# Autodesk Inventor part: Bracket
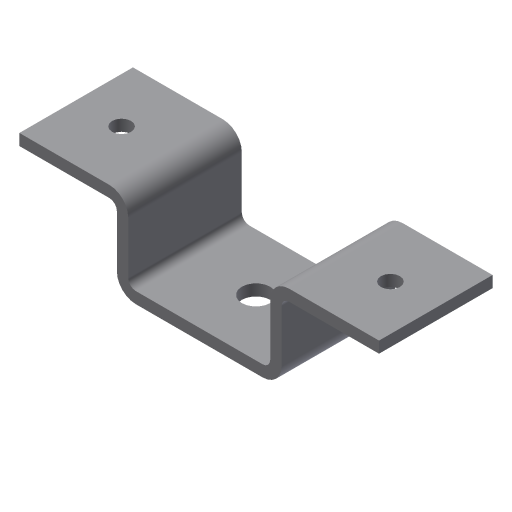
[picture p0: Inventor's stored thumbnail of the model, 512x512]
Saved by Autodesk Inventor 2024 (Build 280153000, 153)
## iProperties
Part Number: Bracket
Document SubType Name: Modeling
Created: 2003-01
Designer: Owner
Density: 1 g/cm^3
Material: Generic
Appearance: Default
Control State: 0
Master: False
Checked Out: False
Shininess: 64.0
Length Units: 11269
Angle Units: 11279
Time Units: 11290
Mass Units: 11283
Length Display Precision: 3
Angle Display Precision: 2
Compacted: True
Density: 0.0
Volumn: 0.0
Area: 0.0
PropertySet Name: Model Information
Author: Owner
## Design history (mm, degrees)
sketch "Sketch2"
  geometry: L1 (487.39, 112.858)-(199.89, 112.858); L2 (199.89, 112.858)-(199.89, -95.142); L3 (199.89, -95.142)-(-175.11, -95.142); L4 (-175.11, -95.142)-(-175.11, 112.858); L5 (-175.11, 112.858)-(-462.61, 112.858); L6 (-462.61, 82.858)-(-205.11, 82.858); L7 (-205.11, 82.858)-(-205.11, -125.142); L8 (-205.11, -125.142)-(229.89, -125.142); L9 (229.89, -125.142)-(229.89, 82.858); L10 (229.89, 82.858)-(487.39, 82.858); L11 (487.39, 112.858)-(487.39, 82.858); L12 (-462.61, 112.858)-(-462.61, 82.858)
  constraints: 24 end point, 5 parallel, 3 perpendicular, 2 collinear, 2 equal length, 1 horizontal, 4 other
  dimensions: "d0" = 375 distance between parallel lines of L4 L2; "d1" = 950 distance of L5.end L1.start; "d2" = 30 distance between parallel lines of L1 L10; "d3" = 238 distance between parallel lines of L5 L8
extrude "Extrusion1" new body sketch "Sketch2" stored distance "d4" = 300; taper "d5" = 0 deg
fillet "Fillet1" dims "d6" = 20
fillet "Fillet2" dims "d7" = 50
sketch "Sketch3"
  geometry: L1 (237.5, 300)-(0, 300) reference; L2 (0, 300)-(0, 0) reference; 1 further point
  dimensions: "d8" = 120 distance from line of L2 point (120, 150); "d9" = 150 distance from line of L1 point (120, 150)
hole "Hole1" sketch "Sketch3" at (120, 150) diameter "d10" = 50; stored, may be unused: countersink angle "d14" = 82 deg, drill point angle "d16" = 118 deg; dims "d11" = 6, "d12" = 4, "d13" = 2, "d15" = 8
pattern_linear "Rectangular Pattern1" dims "d19" = 710
sketch "Sketch4"
  geometry: L1 (0, -300)-(335, -300) reference; 1 further point
  dimensions: "d20" = 150 distance from line of L1 point (167.5, -150)
hole "Hole2" sketch "Sketch4" at (167.5, -150) diameter "d21" = 75; stored, may be unused: countersink angle "d25" = 82 deg, drill point angle "d27" = 118 deg; dims "d22" = 6, "d23" = 4, "d24" = 2, "d26" = 8
body "Solid1"
